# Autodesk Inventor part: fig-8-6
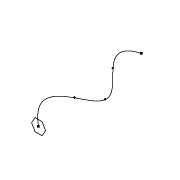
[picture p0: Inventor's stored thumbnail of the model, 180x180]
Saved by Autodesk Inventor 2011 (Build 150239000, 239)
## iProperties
Created: 2006-01
Part Number: fig-8-6
Document SubType Name: Modeling
Designer: CADCIM
Density: 1 g/cm^3
Author: CADCIM
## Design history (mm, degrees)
sketch "Sketch1"
  geometry: 5 further points
  constraints: 5 other
sketch "Sketch2"
  geometry: L1 (-4.728, 0)-(-2.364, 4.094); L2 (-2.364, 4.094)-(2.364, 4.094); L3 (2.364, 4.094)-(4.728, 0); L4 (4.728, 0)-(2.364, -4.094); L5 (2.364, -4.094)-(-2.364, -4.094); L6 (-2.364, -4.094)-(-4.728, 0); 1 further point
  constraints: 12 end point, 13 other
body "Solid1"
